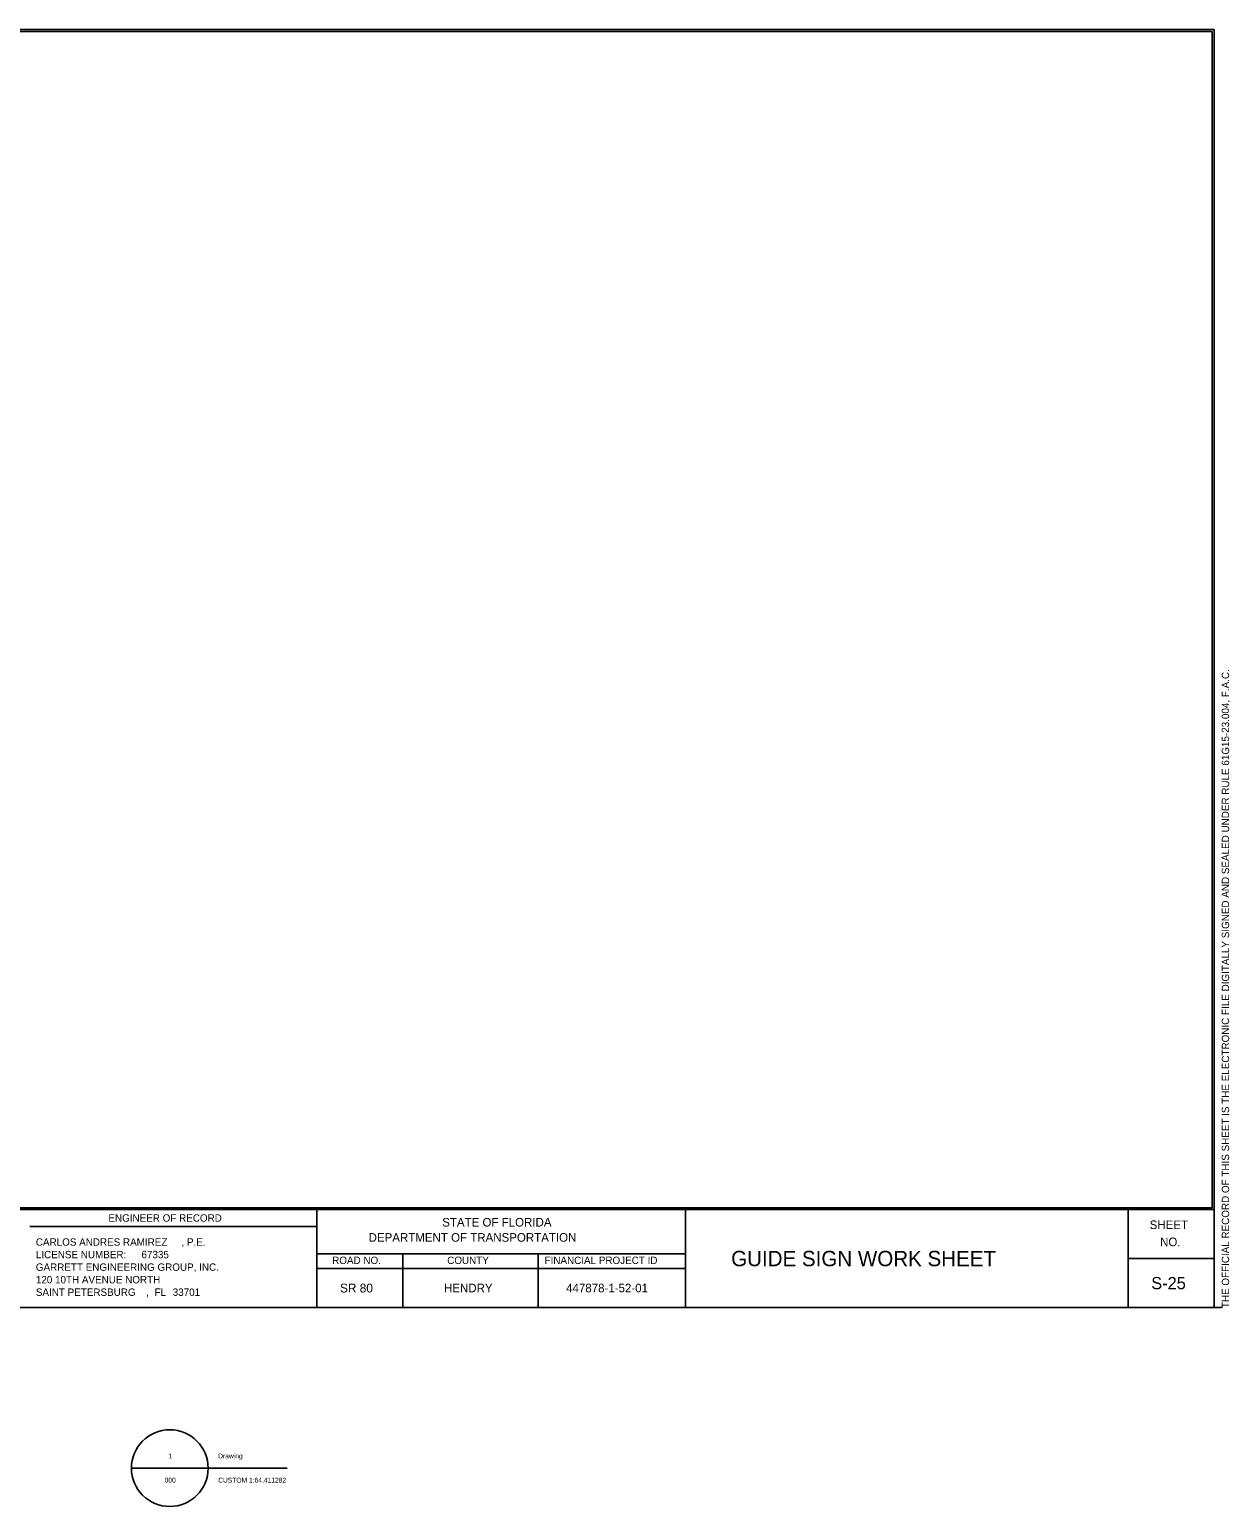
# Model space of a CAD drawing. Extents: x 0.03 to 1.34, y -0.13 to 0.87.
# Drawn here: x 0.526 to 1.34, y -0.131 to 0.871 of the extents above; entities that cross this region are included whole.
import ezdxf

# ---------------------------------------------------------------- set-up
doc = ezdxf.new("R2010")
doc.units = 0
for name, color, linetype in [('ConstLines', 7, 'Continuous'), ('GSBWFill', 7, 'Continuous'), ('GSColorFill', 7, 'Continuous'), ('GSDims', 7, 'Continuous'), ('GSOutline', 7, 'Continuous')]:
    doc.layers.add(name, color=color, linetype=linetype)

msp = doc.modelspace()

# ---------------------------------------------------------------- linework, layer by layer
at = {"layer": 'ConstLines'}
for p, q in [((1.3292, 0.0042), (1.3342, 0.0042)), ((0.595, -0.1046), (0.6471, -0.1046)), ((0.6213, -0.1046), (0.7006, -0.1046))]:
    msp.add_line(p, q, dxfattribs=at)
msp.add_lwpolyline([(0.0471, 0.8694), (1.3277, 0.8694), (1.3277, 0.0718), (0.0471, 0.0718)], close=True, dxfattribs=at)
msp.add_circle((0.6211, -0.1046), 0.026, dxfattribs=at)
at = {"layer": 'GSBWFill'}
for p, q in [((0.7208, 0.0708), (0.7208, 0.0042)), ((0.9708, 0.0042), (0.9708, 0.0708)), ((1.2708, 0.0042), (1.2708, 0.0708)), ((0.5262, 0.0592), (0.7208, 0.0592)), ((0.7208, 0.0408), (0.9708, 0.0408)), ((0.7792, 0.0408), (0.7792, 0.0042)), ((0.8708, 0.0408), (0.8708, 0.0042)), ((0.7208, 0.0308), (0.9708, 0.0308)), ((1.2708, 0.0375), (1.3292, 0.0375))]:
    msp.add_line(p, q, dxfattribs=at)
at = {"layer": 'GSOutline'}
for p, q in [((0.0458, 0.8708), (1.3292, 0.8708)), ((1.3292, 0.8708), (1.3292, 0.0042)), ((0.0458, 0.0708), (1.3292, 0.0708)), ((0.0458, 0.0042), (1.3292, 0.0042))]:
    msp.add_line(p, q, dxfattribs=at)

# ---------------------------------------------------------------- texts
at = {"layer": 'ConstLines'}
for s, height, p in [('1', 0.00328, (0.6202, -0.098)), ('Drawing', 0.00328, (0.6539, -0.098)), ('000', 0.00328, (0.6176, -0.1144)), ('CUSTOM 1:64.411282', 0.003281, (0.6539, -0.1144))]:
    msp.add_text(s, height=height, dxfattribs=at).set_placement(p)
at = {"layer": 'GSColorFill'}
for s, height, rotation, p in [('THE OFFICIAL RECORD OF THIS SHEET IS THE ELECTRONIC FILE DIGITALLY SIGNED AND SEALED UNDER RULE 61G15-23.004, F.A.C.', 0.005, 90, (1.3393, 0.0039)), ('SHEET', 0.00583, 359.8607, (1.2854, 0.0575)), ('NO.', 0.00583, 359.8607, (1.2925, 0.0459))]:
    msp.add_text(s, height=height, rotation=rotation, dxfattribs=at).set_placement(p)
for s, height, p in [('ENGINEER OF RECORD', 0.005, (0.5795, 0.0625)), ('STATE OF FLORIDA', 0.005833, (0.8058, 0.0592)), ('CARLOS ANDRES RAMIREZ', 0.005, (0.5303, 0.0462)), (', P.E.', 0.005, (0.629, 0.0462)), ('DEPARTMENT OF TRANSPORTATION', 0.005833, (0.7559, 0.0489)), ('LICENSE NUMBER: ', 0.005, (0.5303, 0.0377)), ('67335', 0.005, (0.6019, 0.0377)), ('GUIDE SIGN WORK SHEET', 0.010417, (1.0017, 0.0323)), ('GARRETT ENGINEERING GROUP, INC.', 0.005, (0.5303, 0.0292)), ('ROAD NO.', 0.005, (0.7312, 0.0338)), ('COUNTY', 0.005, (0.8092, 0.0338)), ('FINANCIAL PROJECT ID', 0.005, (0.8752, 0.0338)), ('120 10TH AVENUE NORTH', 0.005, (0.5303, 0.0207)), ('SR 80', 0.006, (0.7365, 0.0145)), ('HENDRY', 0.00583, (0.807, 0.0146)), ('447878-1-52-01', 0.005833, (0.8898, 0.0146)), ('SAINT PETERSBURG', 0.005, (0.5303, 0.0122)), (', ', 0.005, (0.6051, 0.0122)), ('FL', 0.005, (0.6108, 0.0122)), ('33701', 0.005, (0.6231, 0.0122))]:
    msp.add_text(s, height=height, dxfattribs=at).set_placement(p)
at = {"layer": 'GSDims'}
msp.add_text('S-25', height=0.0083, dxfattribs=at).set_placement((1.2865, 0.0167))

doc.saveas('drawing.dxf')
